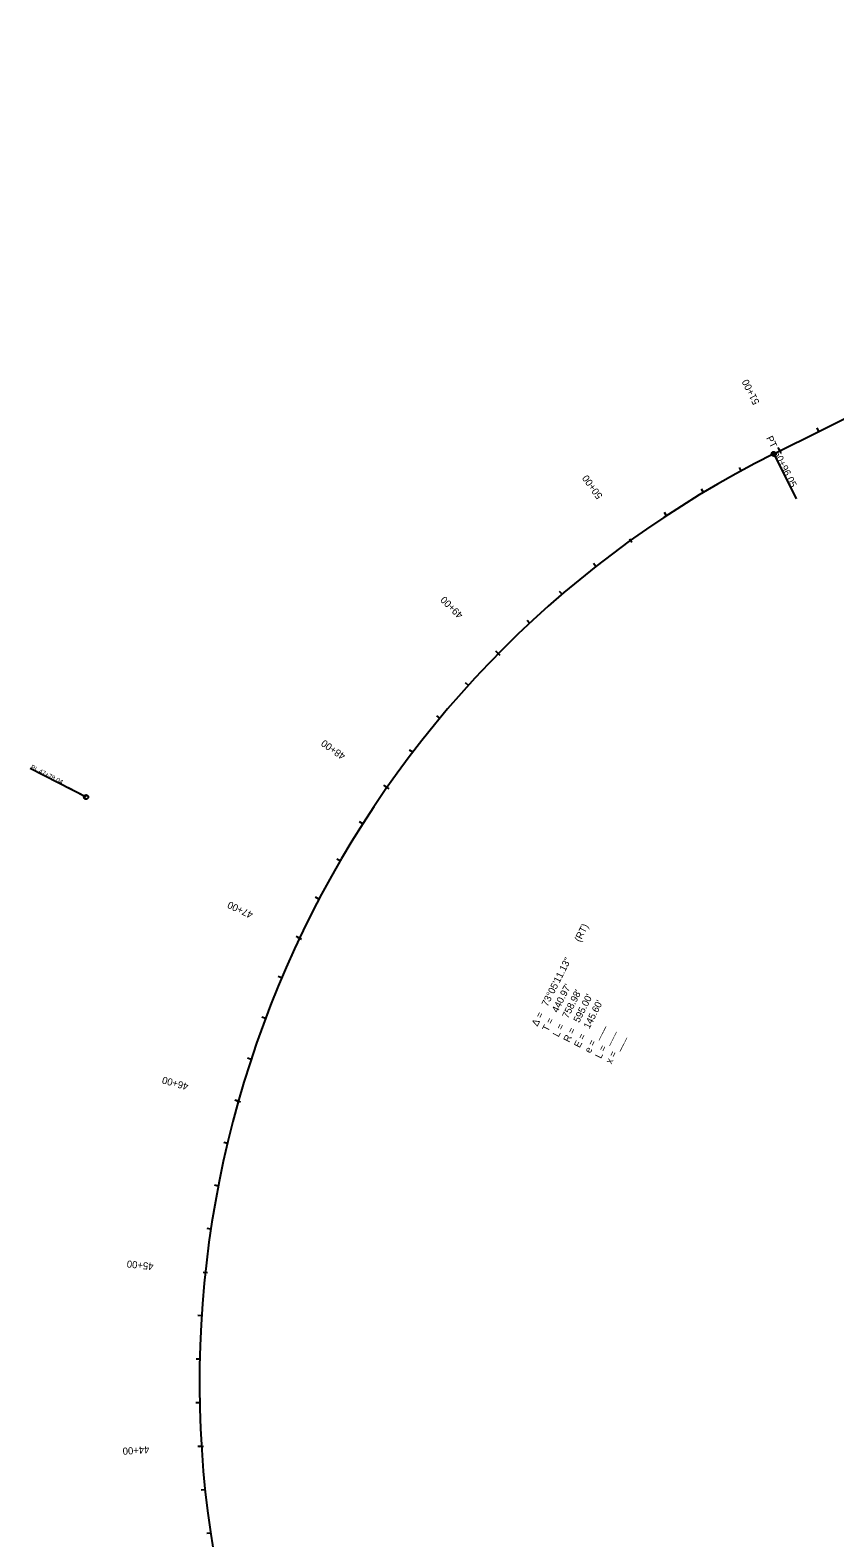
# Model space of a CAD drawing. Extents: x 21487884 to 21488802, y 8074558 to 8076894.
# Drawn here: x 21487884 to 21488345, y 8075997 to 8076862 of the extents above; entities that cross this region are included whole.
import ezdxf

# ---------------------------------------------------------------- set-up
doc = ezdxf.new("R2010")
doc.units = 0
for name, color, linetype in [('PS_BOLT', 7, 'Continuous'), ('PS_DIM', 7, 'Continuous'), ('PS_MID', 7, 'Continuous'), ('PS_SHAPE', 7, 'Continuous')]:
    doc.layers.add(name, color=color, linetype=linetype)

msp = doc.modelspace()

# ---------------------------------------------------------------- linework, layer by layer
at = {"layer": 'PS_BOLT'}
for p, q in [((21488313.84, 8076620.49), (21488312.87, 8076622.45)), ((21488227.46, 8076570.13), (21488228.89, 8076568.14)), ((21488152.29, 8076504.18), (21488150.74, 8076505.72)), ((21488088.35, 8076427.45), (21488086.56, 8076428.7)), ((21488038.14, 8076341.11), (21488036.17, 8076342.04)), ((21488003.09, 8076247.58), (21488000.99, 8076248.17)), ((21487982.95, 8076149.63), (21487985.39, 8076149.37)), ((21487981.93, 8076049.64), (21487979.75, 8076049.51))]:
    msp.add_line(p, q, dxfattribs=at)
at = {"layer": 'PS_DIM'}
for p, q in [((21488310.31, 8076618.73), (21488323.16, 8076592.96)), ((21487915.67, 8076421.97), (21487883.58, 8076438.29)), ((21487915.67, 8076421.97), (21487905.33, 8076427.22)), ((21487915.67, 8076421.97), (21487905.33, 8076427.22))]:
    msp.add_line(p, q, dxfattribs=at)
for centre in [(21488310.31, 8076618.73), (21487915.67, 8076421.97), (21487915.67, 8076421.97), (21487915.67, 8076421.97)]:
    msp.add_circle(centre, 1.25, dxfattribs=at)
at = {"layer": 'PS_MID'}
for p, q in [((21488336.21, 8076631.65), (21488335.24, 8076633.6)), ((21488313.29, 8076621.59), (21488314.39, 8076619.4)), ((21488291.64, 8076609.01), (21488290.59, 8076610.93)), ((21488269.93, 8076596.61), (21488268.81, 8076598.48)), ((21488248.76, 8076583.31), (21488247.56, 8076585.14)), ((21488227.46, 8076570.13), (21488228.89, 8076568.14)), ((21488208.2, 8076554.11), (21488206.85, 8076555.83)), ((21488188.87, 8076538.26), (21488187.45, 8076539.91)), ((21488170.22, 8076521.6), (21488168.73, 8076523.2)), ((21488151.42, 8076505.04), (21488153.17, 8076503.32)), ((21488135.11, 8076486.03), (21488133.5, 8076487.49)), ((21488118.71, 8076467.16), (21488117.03, 8076468.56)), ((21488103.11, 8076447.63), (21488101.38, 8076448.95)), ((21488087.35, 8076428.15), (21488089.35, 8076426.75)), ((21488074.45, 8076406.68), (21488072.61, 8076407.85)), ((21488061.43, 8076385.33), (21488059.54, 8076386.43)), ((21488049.32, 8076363.46), (21488047.39, 8076364.48)), ((21488037.04, 8076341.63), (21488039.25, 8076340.58)), ((21488027.91, 8076318.3), (21488025.9, 8076319.15)), ((21488018.65, 8076295.08), (21488016.6, 8076295.84)), ((21488010.37, 8076271.49), (21488008.29, 8076272.17)), ((21488001.91, 8076247.91), (21488004.27, 8076247.24)), ((21487996.82, 8076223.38), (21487994.69, 8076223.88)), ((21487991.57, 8076198.94), (21487989.42, 8076199.35)), ((21487987.35, 8076174.3), (21487985.19, 8076174.62)), ((21487982.95, 8076149.63), (21487985.39, 8076149.37)), ((21487982.04, 8076124.6), (21487979.86, 8076124.74)), ((21487980.95, 8076099.62), (21487978.77, 8076099.67)), ((21487980.91, 8076074.62), (21487978.73, 8076074.58)), ((21487980.7, 8076049.57), (21487983.15, 8076049.72)), ((21487983.99, 8076024.73), (21487981.82, 8076024.51)), ((21487987.09, 8075999.93), (21487984.93, 8075999.61))]:
    msp.add_line(p, q, dxfattribs=at)
at = {"layer": 'PS_SHAPE'}
msp.add_line((21488310.31, 8076618.73), (21488797.63, 8076861.71), dxfattribs=at)
msp.add_arc((21488575.8, 8076086.25), 595, 116.50071, 189.58714, dxfattribs=at)

# ---------------------------------------------------------------- texts
at = {"layer": 'PS_BOLT'}
for s, rotation, p in [('50+00', 125.74979, (21488212.3, 8076594.68)), ('45+00', 173.8975, (21487954.56, 8076154.72))]:
    msp.add_text(s, height=4.08, rotation=rotation, dxfattribs=at).set_placement(p)
at = {"layer": 'PS_DIM'}
for s, height, rotation, p in [('PT', 4.008, 296.50071, (21488305.84, 8076627.87)), ('50+96.05', 4.008, 296.50071, (21488310.16, 8076619.19)), ('PI ', 2.592, 333.04392, (21487883.6, 8076438.33)), ('47+78.04', 2.592, 333.04392, (21487888.21, 8076435.99)), (' (RT)', 4.008, 63.04392, (21488198.56, 8076337.21)), ('73°05\'11.13"', 4.008, 63.04392, (21488180.42, 8076301.56)), ("440.97'", 4.008, 63.04392, (21488186.27, 8076298.02)), ("758.98'", 4.008, 63.04392, (21488192.23, 8076294.71)), ("595.00'", 4.008, 63.04392, (21488198.63, 8076292.27)), ('Δ = ', 4.008, 63.04392, (21488174.67, 8076290.25)), ("145.60'", 4.008, 63.04392, (21488204.49, 8076288.76)), ('T = ', 4.008, 63.04392, (21488180.75, 8076287.16)), ('L = ', 4.008, 63.04392, (21488186.82, 8076284.07)), ('e = ___ ', 4.008, 63.04392, (21488205.04, 8076274.8)), ('R = ', 4.008, 63.04392, (21488192.89, 8076280.98)), ('E = ', 4.008, 63.04392, (21488198.97, 8076277.89)), ('L = ___', 4.008, 63.04392, (21488211.11, 8076271.71)), ('x = ___', 4.008, 63.04392, (21488217.19, 8076268.63))]:
    msp.add_text(s, height=height, rotation=rotation, dxfattribs=at).set_placement(p)
at = {"layer": 'PS_MID'}
for s, rotation, p in [('51+00', 116.50071, (21488302.28, 8076648.25)), ('50+00', 125.74979, (21488212.3, 8076594.68)), ('49+00', 135.37933, (21488132.37, 8076526.71)), ('48+00', 145.00887, (21488064.94, 8076446.33)), ('47+00', 154.63842, (21488011.91, 8076355.8)), ('46+00', 164.26796, (21487974.76, 8076257.67)), ('45+00', 173.8975, (21487954.56, 8076154.72)), ('44+00', 183.52705, (21487951.86, 8076049.84))]:
    msp.add_text(s, height=4.08, rotation=rotation, dxfattribs=at).set_placement(p)

doc.saveas('drawing.dxf')
